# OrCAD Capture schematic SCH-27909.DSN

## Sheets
1 4. Power Supply, Battery, uSD: size C; title: FRDM-FXS-MULTI; rev: C; company: Freescale Semiconductor; note: SCH-27909 | PDF: SPF-27909; note: 6501 William Cannon Drive West; note: Austin, TX 78735-8598
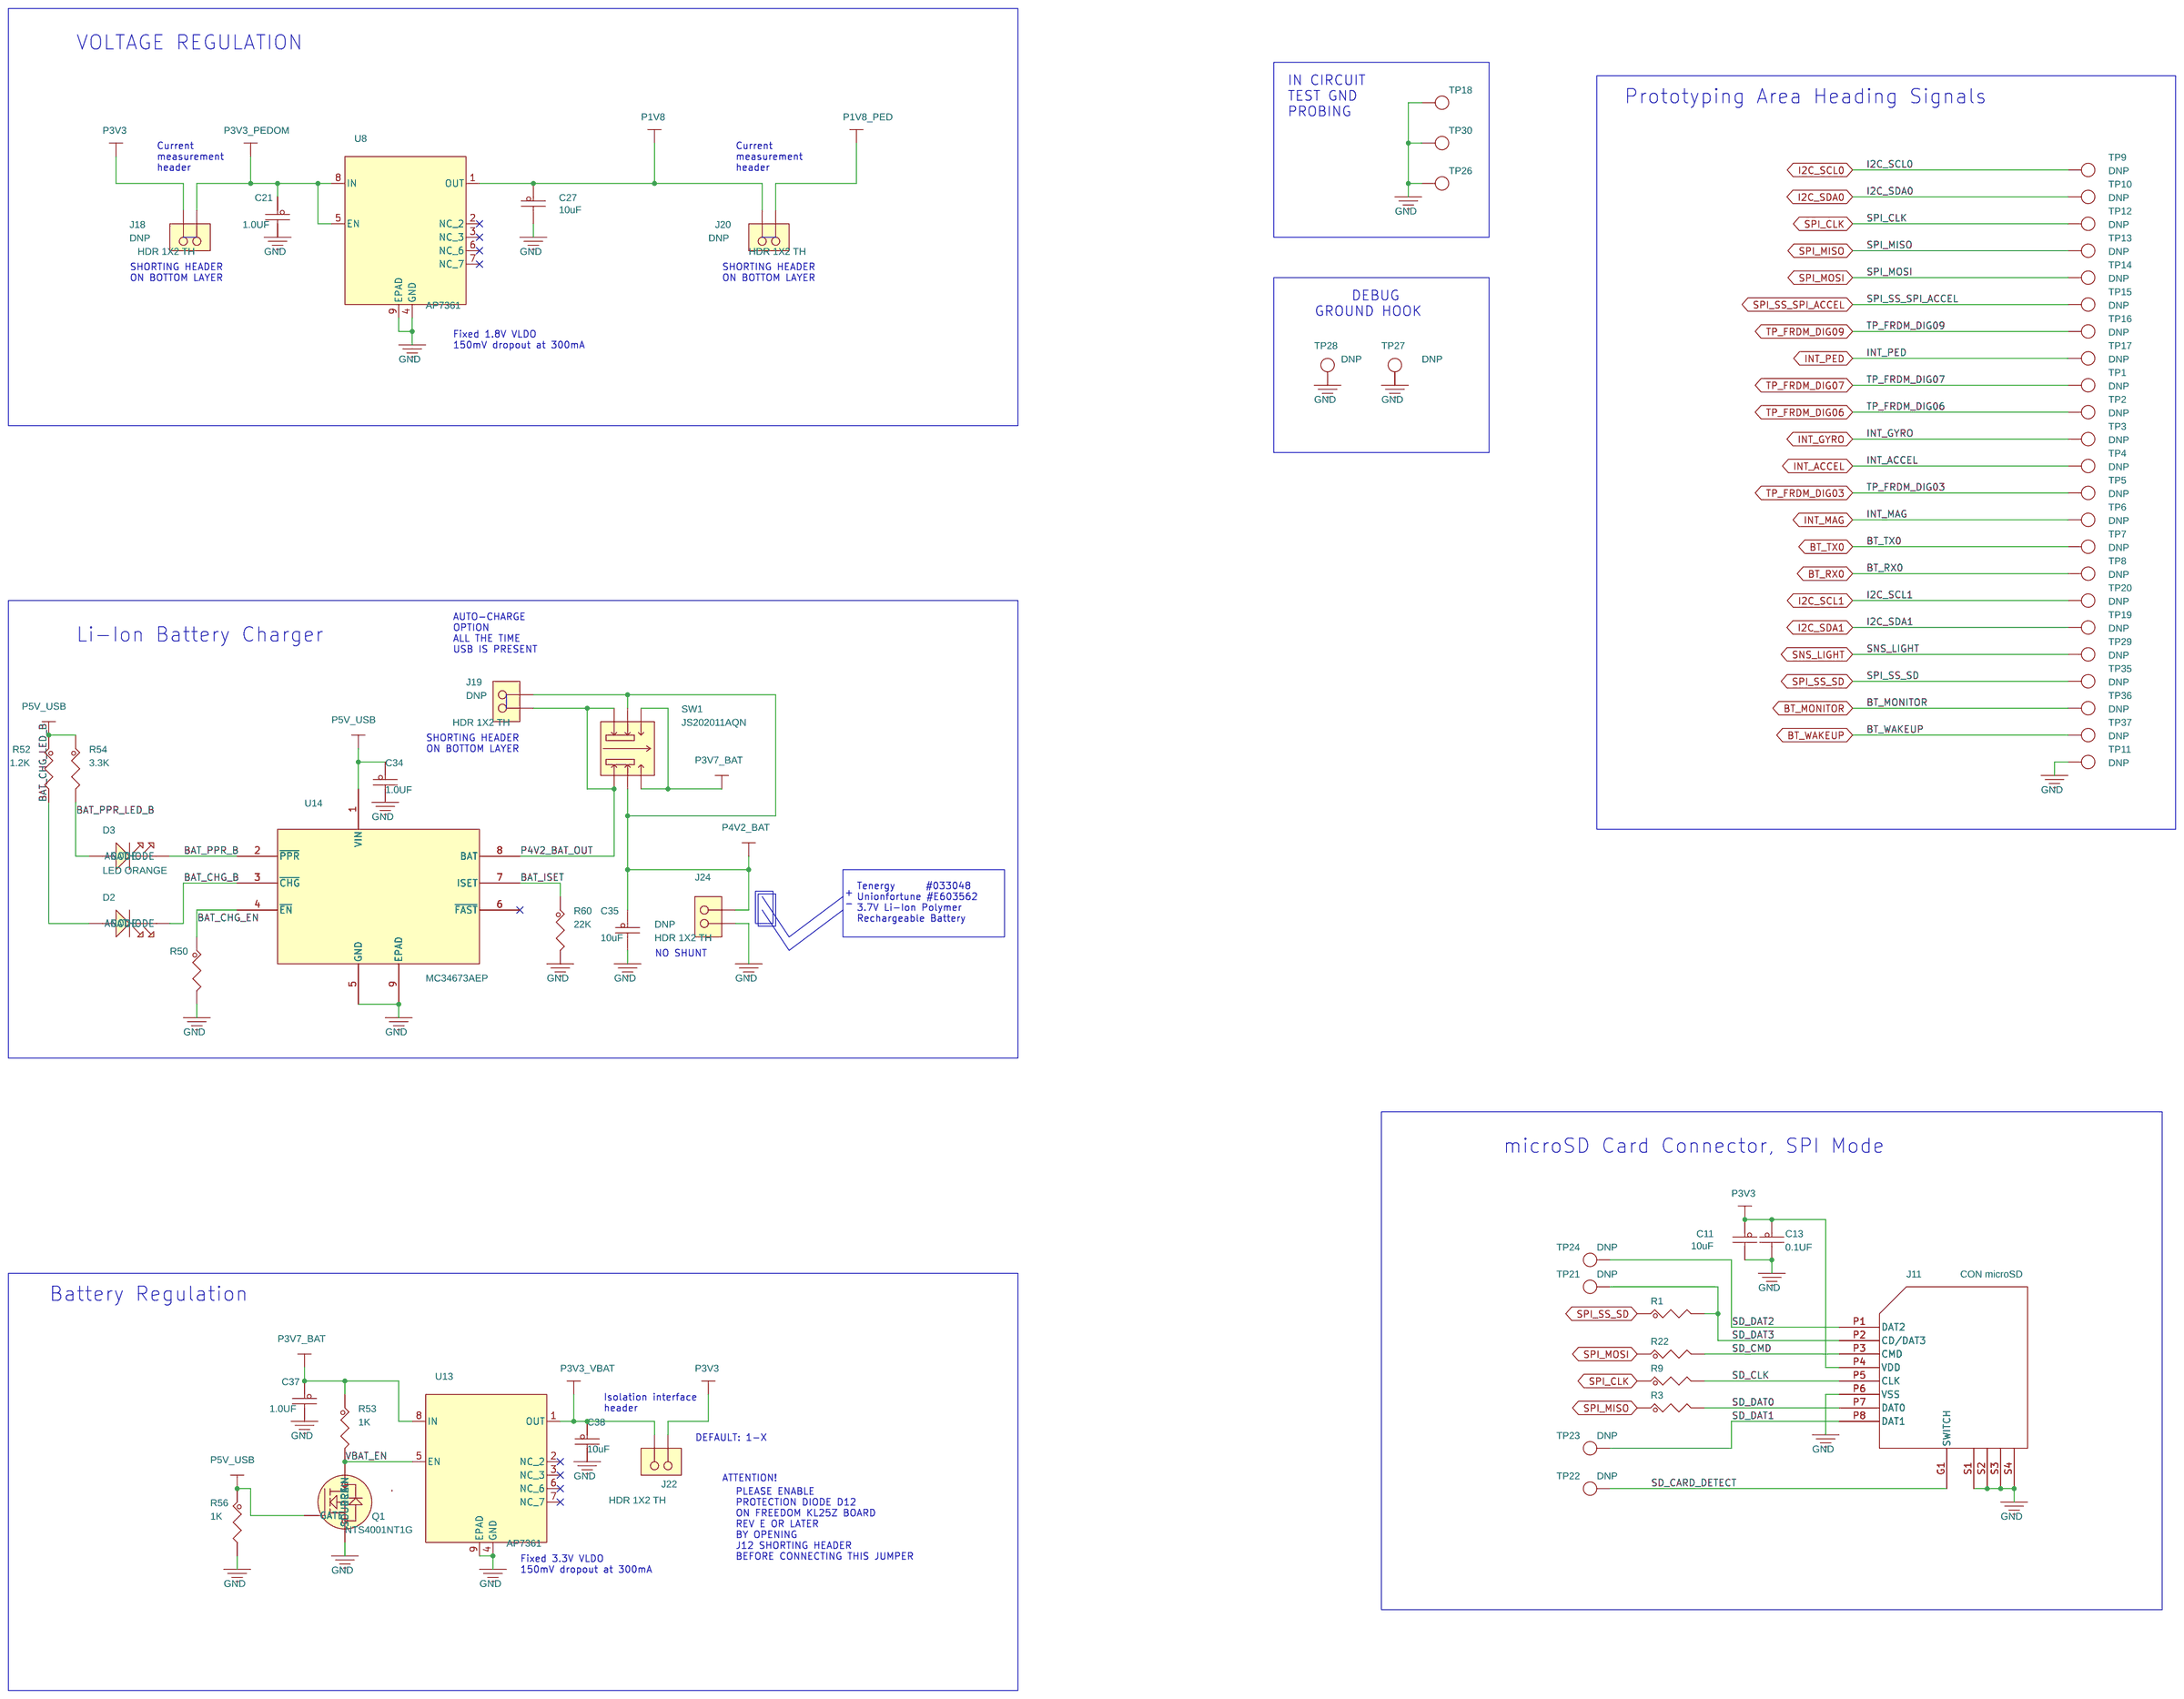
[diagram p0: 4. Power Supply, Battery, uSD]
2 1. Title Page
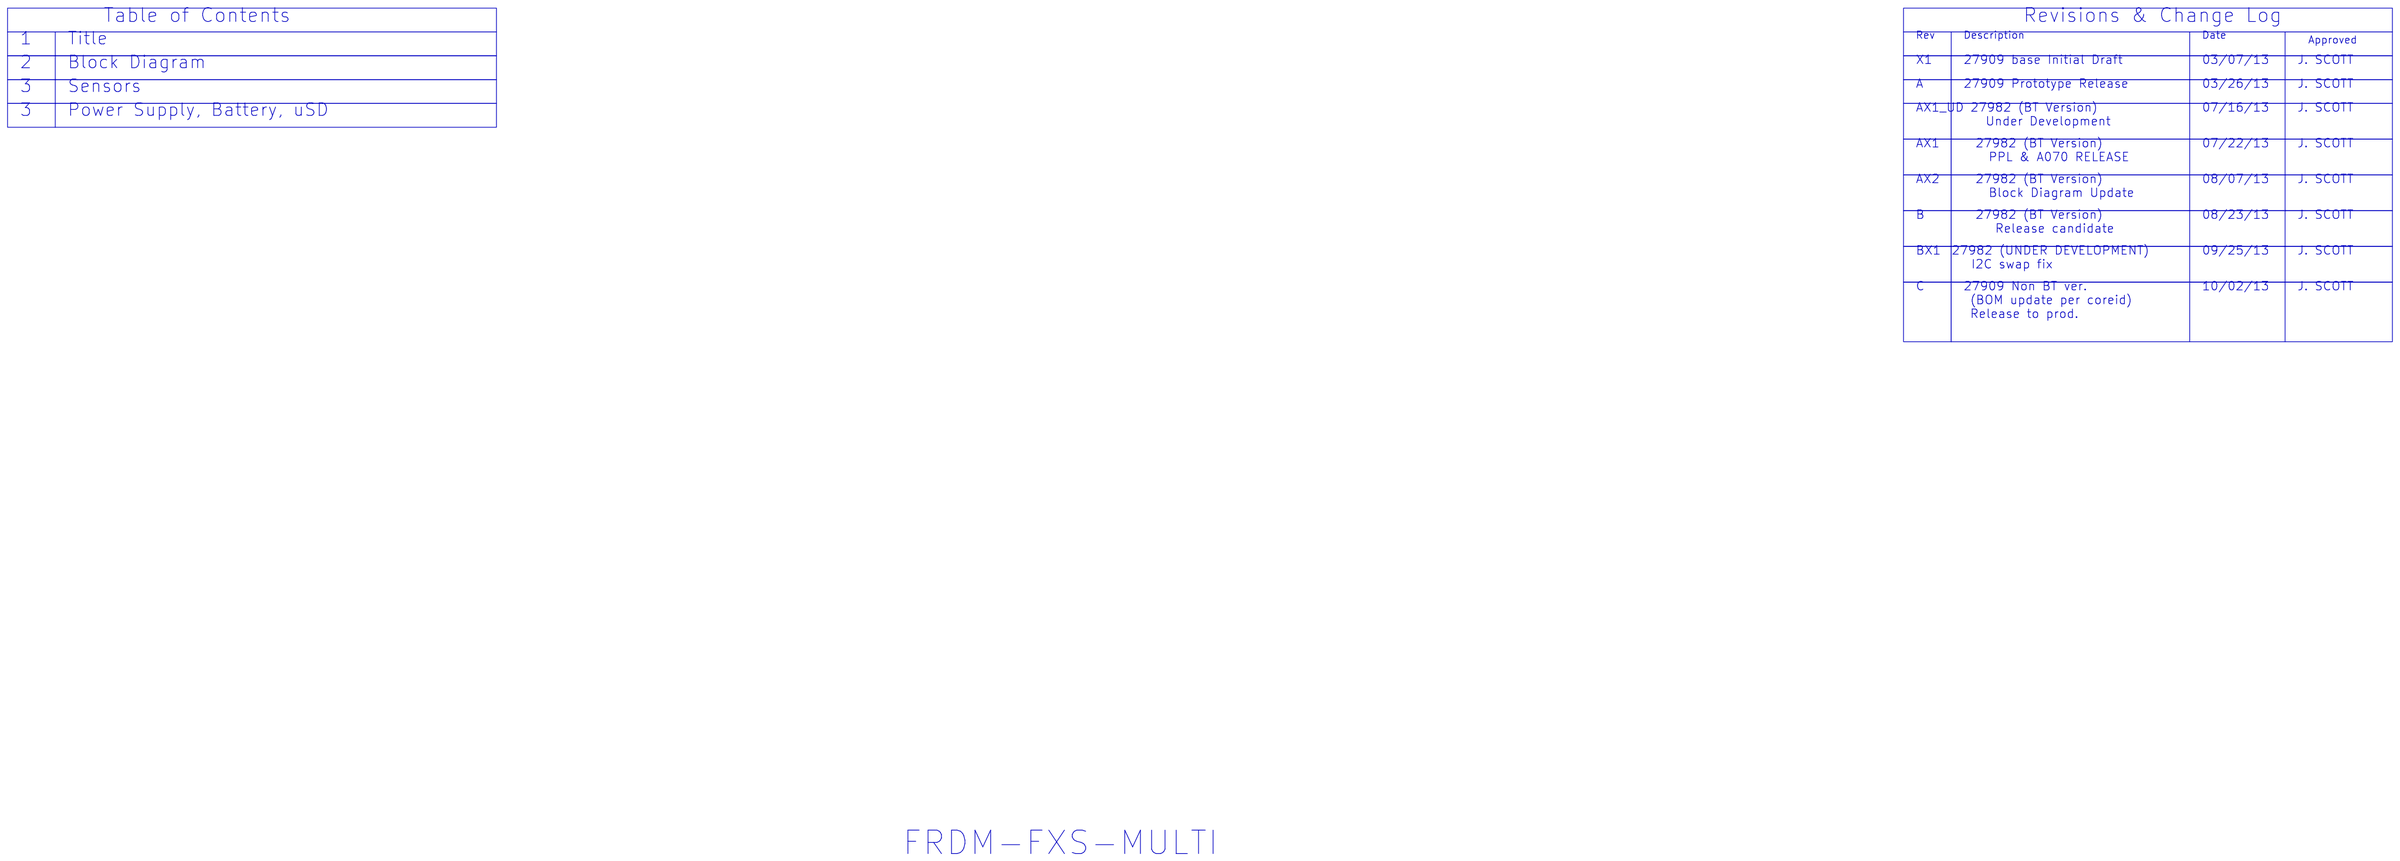
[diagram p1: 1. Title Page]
3 2. Block Diagram
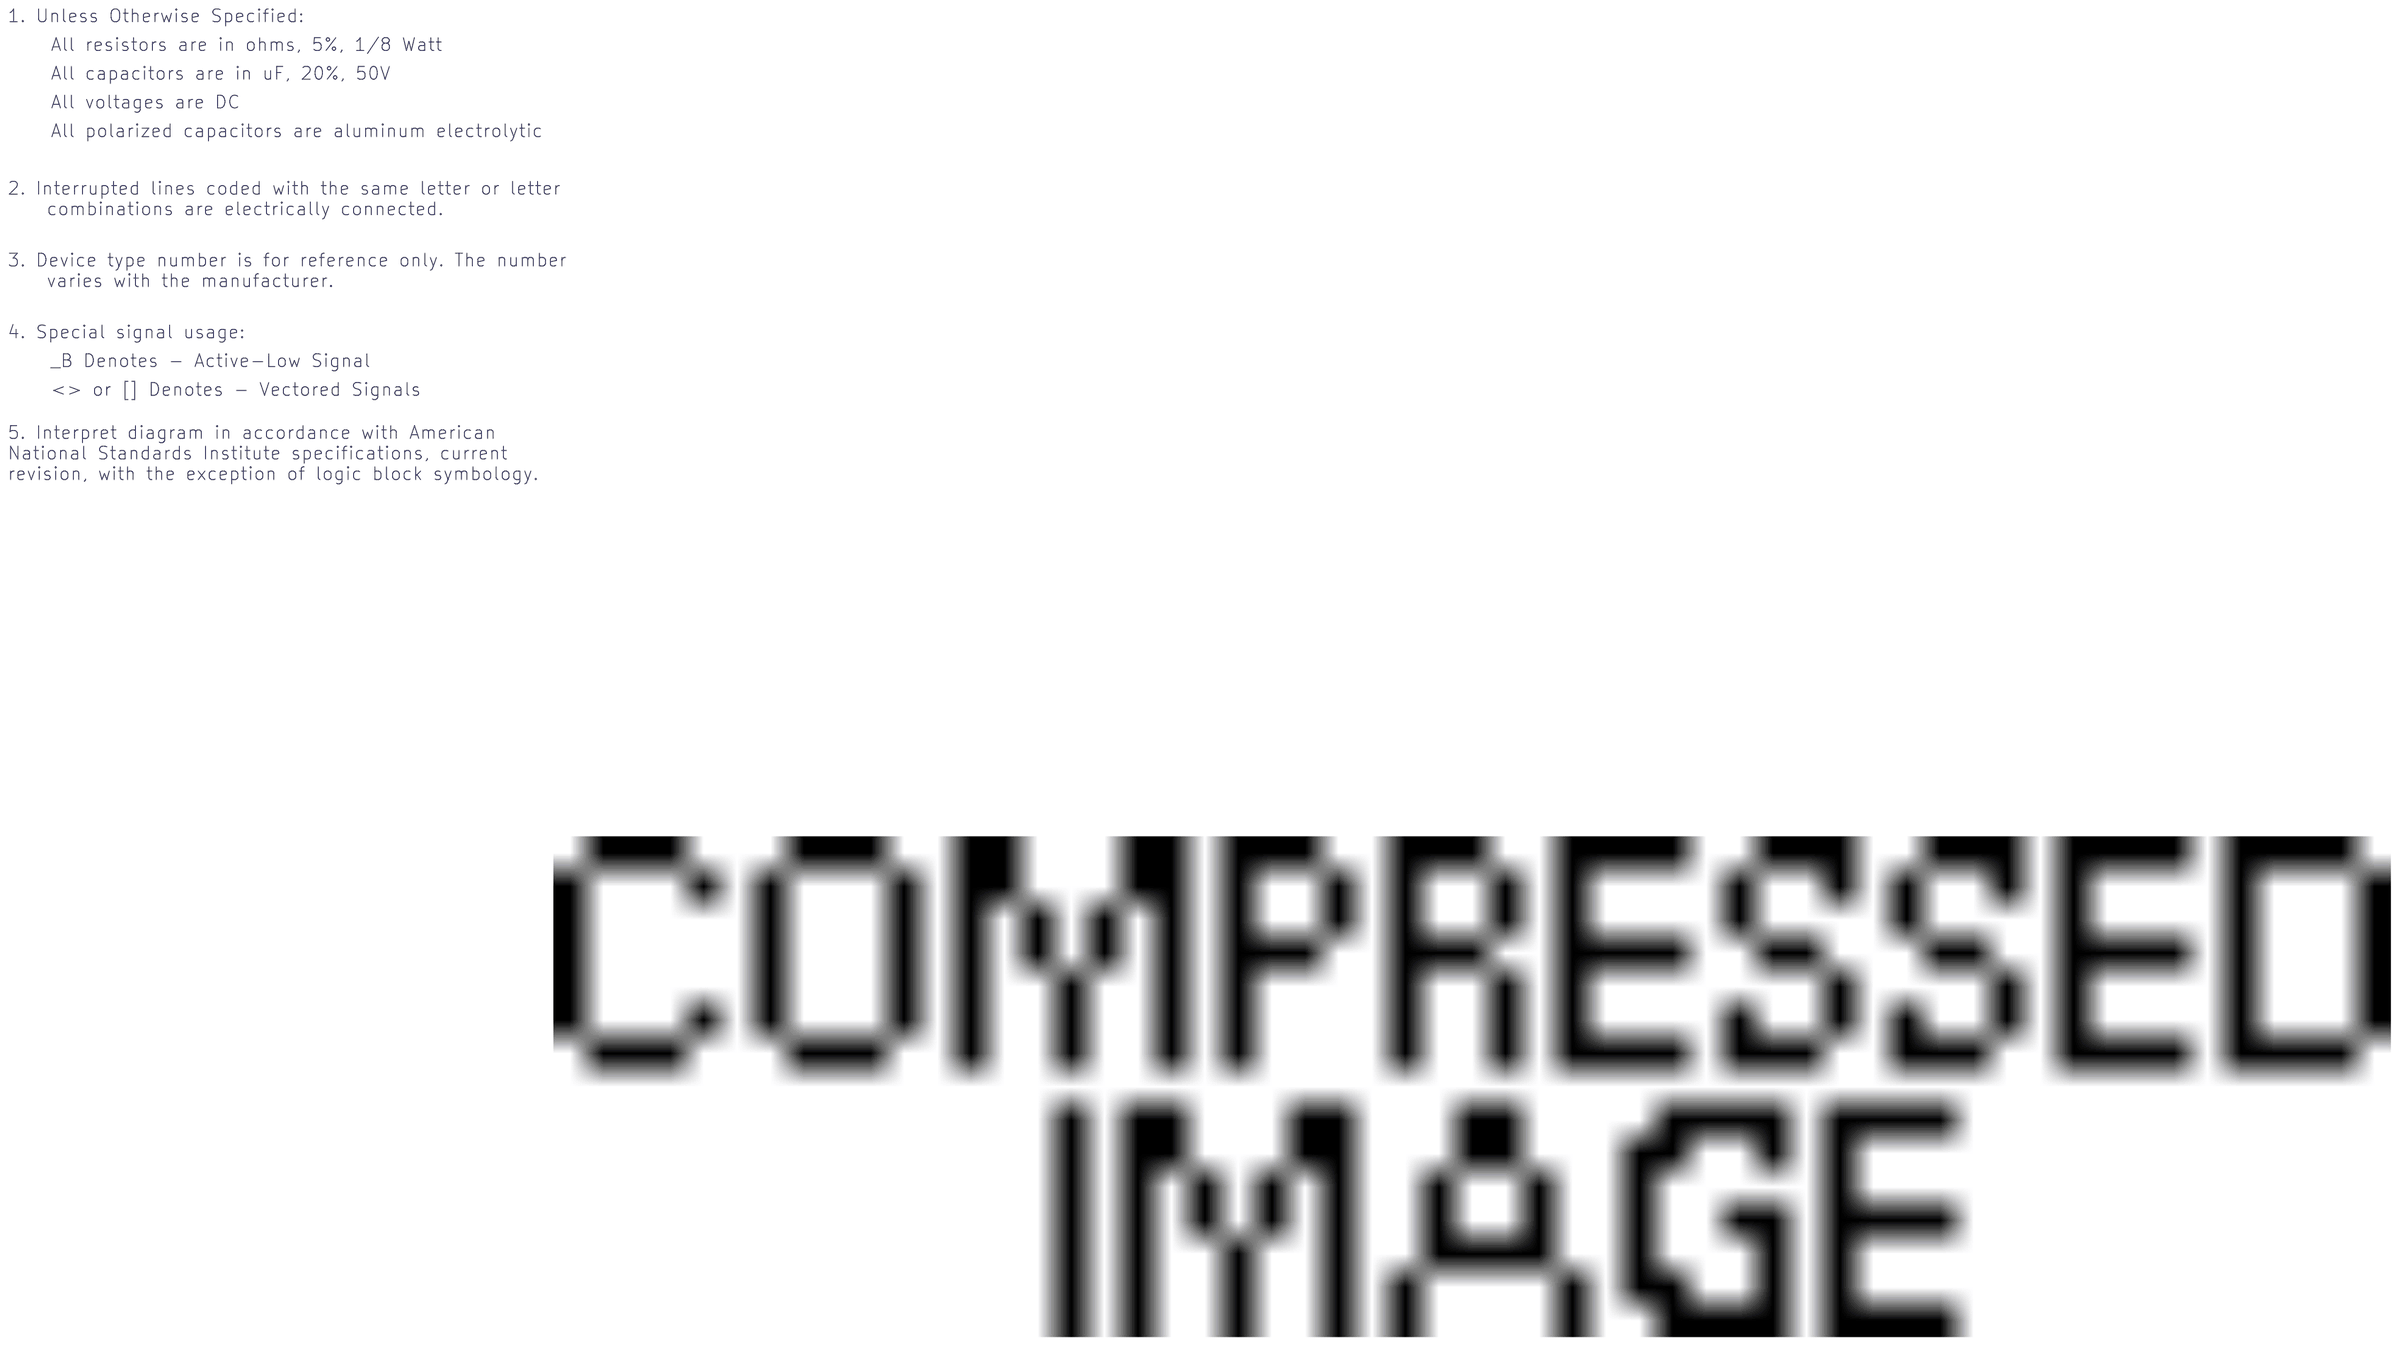
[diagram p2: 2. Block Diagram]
4 3. Sensors: size C
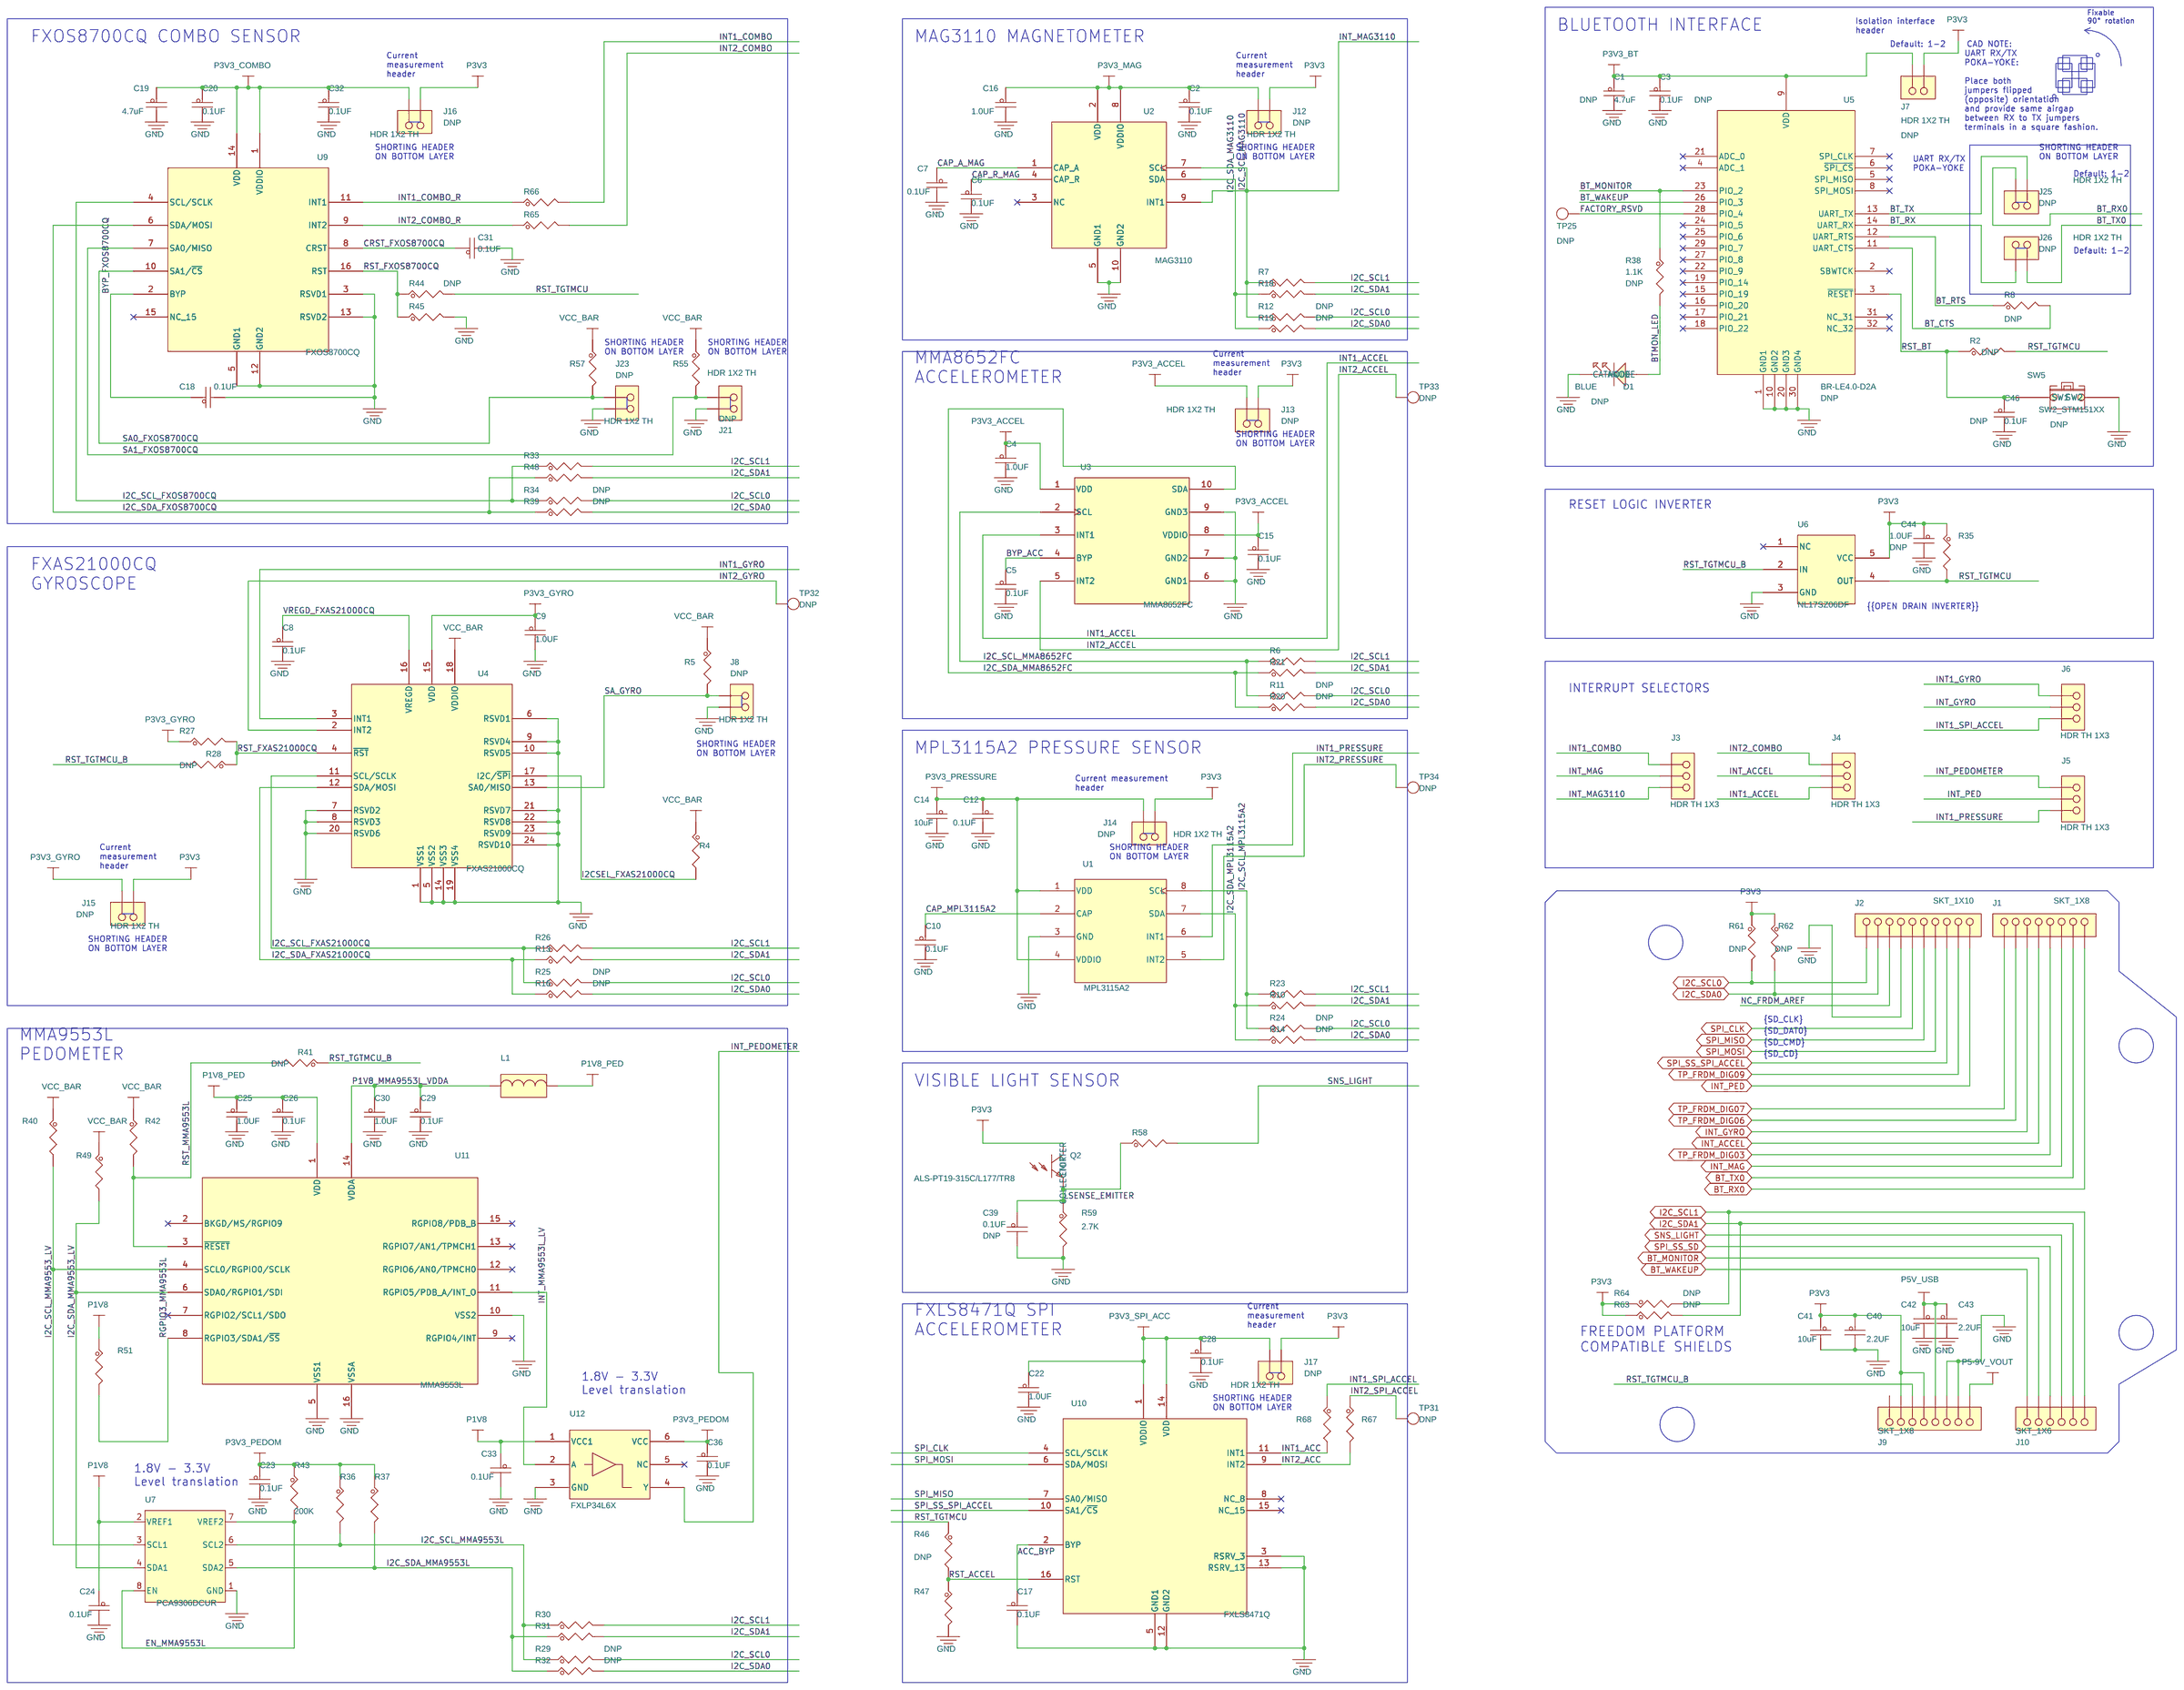
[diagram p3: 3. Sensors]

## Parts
sheet 3. Sensors
C1  4.7uF  [CC0402_25]
C2  0.1UF  [CC0402_25]
C3  0.1UF  [CC0402_25]
C4  1.0UF  [CC0402_25]
C5  0.1UF  [CC0402_25]
C6  0.1UF  [CC0402_25]
C7  0.1UF  [CC0402_25]
C8  0.1UF  [CC0402_25]
C9  1.0UF  [CC0402_25]
C10  0.1UF  [CC0402_25]
C12  0.1UF  [CC0402_25]
C14  10uF  [CC0603_OV]
C15  0.1UF  [CC0402_25]
C16  1.0UF  [CC0402_25]
C17  0.1UF  [CC0402_25]
C18  0.1UF  [CC0402_25]
C19  4.7uF  [CC0402_25]
C20  0.1UF  [CC0402_25]
C22  1.0UF  [CC0402_25]
C23  0.1UF  [CC0402_25]
C24  0.1UF  [CC0402_25]
C25  1.0UF  [CC0402_25]
C26  0.1UF  [CC0402_25]
C28  0.1UF  [CC0402_25]
C29  0.1UF  [CC0402_25]
C30  1.0UF  [CC0402_25]
C31  0.1UF  [CC0402_25]
C32  0.1UF  [CC0402_25]
C33  0.1UF  [CC0402_25]
C36  0.1UF  [CC0402_25]
C39  0.1UF  [CC0402_25]
C40  2.2UF  [CC0603_OV]
C41  10uF  [CC0603_OV]
C42  10uF  [CC0603_OV]
C43  2.2UF  [CC0603_OV]
C44  1.0UF  [CC0402_25]
C46  0.1UF  [CC0402_25]
D1  BLUE  [LED_0603]
J1  SKT_1X8  [con_skt1x8_th]
J2  SKT_1X10  [con_skt1x10_th]
J3  HDR TH 1X3  [HDR103]
J4  HDR TH 1X3  [HDR103]
J5  HDR TH 1X3  [HDR103]
J6  HDR TH 1X3  [HDR103]
J7  HDR 1X2 TH  [HDR102]
J8  HDR 1X2 TH  [SH_HDR102_BOTTOM]
J9  SKT_1X8  [con_skt1x8_th]
J10  SKT_1X6  [con_skt1x6_th]
J12  HDR 1X2 TH  [SH_HDR102_BOTTOM]
J13  HDR 1X2 TH  [SH_HDR102_BOTTOM]
J14  HDR 1X2 TH  [SH_HDR102_BOTTOM]
J15  HDR 1X2 TH  [SH_HDR102_BOTTOM]
J16  HDR 1X2 TH  [SH_HDR102_BOTTOM]
J17  HDR 1X2 TH  [SH_HDR102_BOTTOM]
J21  HDR 1X2 TH  [SH_HDR102_BOTTOM]
J23  HDR 1X2 TH  [SH_HDR102_BOTTOM]
J25  HDR 1X2 TH  [SH_HDR102_BOTTOM]
J26  HDR 1X2 TH  [SH_HDR102_BOTTOM]
L1  330 OHM  [IND_0805]
Q2  ALS-PT19-315C/L177/TR8  [phtrans_1p9x1]
R2  0  [RC0603_OV]
R4  10K  [RC0603_OV]
R5  10K  [RC0603_OV]
R6  0  [RC0603_OV]
R7  0  [RC0603_OV]
R8  0  [RC0603_OV]
R10  0  [RC0603_OV]
R11  0  [RC0603_OV]
R12  0  [RC0603_OV]
R13  0  [RC0603_OV]
R14  0  [RC0603_OV]
R16  0  [RC0603_OV]
R18  0  [RC0603_OV]
R19  0  [RC0603_OV]
R20  0  [RC0603_OV]
R21  0  [RC0603_OV]
R23  0  [RC0603_OV]
R24  0  [RC0603_OV]
R25  0  [RC0603_OV]
R26  0  [RC0603_OV]
R27  10K  [RC0603_OV]
R28  0  [RC0603_OV]
R29  0  [RC0603_OV]
R30  0  [RC0603_OV]
R31  0  [RC0603_OV]
R32  0  [RC0603_OV]
R33  0  [RC0603_OV]
R34  0  [RC0603_OV]
R35  10K  [RC0603_OV]
R36  4.7K  [RC0603_OV]
R37  4.7K  [RC0603_OV]
R38  1.1K  [RC0603_OV]
R39  0  [RC0603_OV]
R40  4.7K  [RC0603_OV]
R41  0  [RC0603_OV]
R42  4.7K  [RC0603_OV]
R43  200K  [RC0603_OV]
R44  0  [RC0603_OV]
R45  10K  [RC0603_OV]
R46  0  [RC0603_OV]
R47  10K  [RC0603_OV]
R48  0  [RC0603_OV]
R49  4.7K  [RC0603_OV]
R51  4.7K  [RC0603_OV]
R55  10K  [RC0603_OV]
R57  10K  [RC0603_OV]
R58  0  [RC0603_OV]
R59  2.7K  [RC0603_OV]
R61  10K  [RC0603_OV]
R62  10K  [RC0603_OV]
R63  10K  [RC0603_OV]
R64  10K  [RC0603_OV]
R65  0  [RC0603_OV]
R66  0  [RC0603_OV]
R67  0  [RC0603_OV]
R68  0  [RC0603_OV]
SW5  SW2_STM151XX  [sw2_4x3mm_sm]
TP25  TPAD_030  [TPAD_030]
TP31  TPAD_030  [TPAD_030]
TP32  TPAD_030  [TPAD_030]
TP33  TPAD_030  [TPAD_030]
TP34  TPAD_030  [TPAD_030]
U1  MPL3115A2  [LGA8_1P25_3X5_0P5]
U2  MAG3110  [DFN_10_0P4_2X2_A]
U3  MMA8652FC  [DFN_10_0P4_2X2]
U4  FXAS21000CQ  [QFN24_0P5_4X4_ASYM_EXP]
U5  BR-LE4.0-D2A  [bluetooth_module_18x12]
U6  NL17SZ06DF  [sot353]
U7  PCA9306DCUR  [ssop8_dcu]
U9  FXOS8700CQ  [qfn5x3_0p5_3x3]
U10  FXLS8471Q  [QFN5X3_0P5_3X3]
U11  MMA9553L  [LGA16_0P5_3X3_A]
U12  FXLP34L6X  [MICROPAK_6P]
sheet 4. Power Supply, Battery, uSD
C11  10uF  [CC0603_OV]
C13  0.1UF  [CC0402_25]
C21  1.0UF  [CC0402_25]
C27  10uF  [CC0603_OV]
C34  1.0UF  [CC0402_25]
C35  10uF  [CC0603_OV]
C37  1.0UF  [CC0402_25]
C38  10uF  [CC0603_OV]
D2  LED GREEN  [LED_0603]
D3  LED ORANGE  [LED_0603]
J11  CON microSD  [con8_sdcard_push_sm]
J18  HDR 1X2 TH  [SH_HDR102_BOTTOM]
J19  HDR 1X2 TH  [SH_HDR102_BOTTOM]
J20  HDR 1X2 TH  [SH_HDR102_BOTTOM]
J22  HDR 1X2 TH  [HDR102]
J24  HDR 1X2 TH  [HDR102]
Q1  NTS4001NT1G  [sc70_3]
R1  0  [RC0603_OV]
R3  0  [RC0603_OV]
R9  0  [RC0603_OV]
R22  0  [RC0603_OV]
R50  0  [RC0603_OV]
R52  1.2K  [RC0603_OV]
R53  1K  [RC0402_25]
R54  3.3K  [RC0603_OV]
R56  1K  [RC0402_25]
R60  22K  [RC0603_OV]
SW1  JS202011AQN  [sw6_2p5_9x3p6]
TP1  TEST POINT WHITE  [TEST_LOOP]
TP2  TEST POINT WHITE  [TEST_LOOP]
TP3  TEST POINT WHITE  [TEST_LOOP]
TP4  TEST POINT WHITE  [TEST_LOOP]
TP5  TEST POINT WHITE  [TEST_LOOP]
TP6  TEST POINT WHITE  [TEST_LOOP]
TP7  TEST POINT WHITE  [TEST_LOOP]
TP8  TEST POINT WHITE  [TEST_LOOP]
TP9  TEST POINT WHITE  [TEST_LOOP]
TP10  TEST POINT WHITE  [TEST_LOOP]
TP11  TEST POINT WHITE  [TEST_LOOP]
TP12  TEST POINT WHITE  [TEST_LOOP]
TP13  TEST POINT WHITE  [TEST_LOOP]
TP14  TEST POINT WHITE  [TEST_LOOP]
TP15  TEST POINT WHITE  [TEST_LOOP]
TP16  TEST POINT WHITE  [TEST_LOOP]
TP17  TEST POINT WHITE  [TEST_LOOP]
TP18  TPAD_030  [TPAD_030]
TP19  TEST POINT WHITE  [TEST_LOOP]
TP20  TEST POINT WHITE  [TEST_LOOP]
TP21  TEST POINT WHITE  [TEST_LOOP]
TP22  TEST POINT WHITE  [TEST_LOOP]
TP23  TEST POINT WHITE  [TEST_LOOP]
TP24  TEST POINT WHITE  [TEST_LOOP]
TP26  TPAD_030  [TPAD_030]
TP27  TEST POINT WHITE  [TEST_LOOP]
TP28  TEST POINT WHITE  [TEST_LOOP]
TP29  TEST POINT WHITE  [TEST_LOOP]
TP30  TPAD_030  [TPAD_030]
TP35  TEST POINT WHITE  [TEST_LOOP]
TP36  TEST POINT WHITE  [TEST_LOOP]
TP37  TEST POINT WHITE  [TEST_LOOP]
U8  AP7361  [tdfn8_0p65_3x3]
U13  AP7361  [tdfn8_0p65_3x3]
U14  MC34673AEP  [DFN_8_0P5_2X3]

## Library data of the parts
C1 = CAP_NP: CAP CER 4.7UF 6.3V 20% X5R 0402; AGILE_PN: 150-78463; ASSY_OPT: DNP; CAD_APPROVED: Yes; FPLIST: CC0402_25,CC0402_HD,0402_CC; HEIGHT: 0.65MM; MFG_NAME01: VENKEL COMPANY; MFG_PN01: C0402X5R6R3-475MNP; ROHS: Yes; Tolerance: 20%; VOLTAGE: 6.3V
C2 C5-C8 C10 C12 C13 C15 C17 C18 C20 C23 C24 C26 C28 C29 C31-C33 C36 = CAP_NP: CAP CER 0.1UF 10V 10% X5R 0402; AGILE_PN: 150-75634; CAD_APPROVED: Yes; FPLIST: CC0402_25,CC0402_HD,0402_CC; HEIGHT: 0.64MM; MFG_NAME01: KEMET; MFG_PN01: C0402C104K8PAC; ROHS: Yes; Tolerance: 10%; VOLTAGE: 10V
C3 C39 C46 = CAP_NP: CAP CER 0.1UF 10V 10% X5R 0402; AGILE_PN: 150-75634; ASSY_OPT: DNP; CAD_APPROVED: Yes; FPLIST: CC0402_25,CC0402_HD,0402_CC; HEIGHT: 0.64MM; MFG_NAME01: KEMET; MFG_PN01: C0402C104K8PAC; ROHS: Yes; Tolerance: 10%; VOLTAGE: 10V
C4 C9 C16 C21 C22 C25 C30 C34 C37 = CAP_NP: CAP CER 1.0UF 10V 10% X5R 0402; AGILE_PN: 150-75772; CAD_APPROVED: Yes; FPLIST: CC0402_25,CC0402_HD,0402_CC; HEIGHT: 0.6MM; MFG_NAME01: YAGEO AMERICA; MFG_PN01: CC0402KRX5R6BB105; ROHS: Yes; VOLTAGE: 10V
C11 C14 C27 C35 C38 C41 C42 = CAP_NP: CAP CER 10UF 10V 20% X5R 0603; AGILE_PN: 150-78609; CAD_APPROVED: Yes; FPLIST: CC0603_OV,CC0603,0603_CC; HEIGHT: 1.016MM; MFG_NAME01: TAIYO YUDEN; MFG_PN01: LMK107BJ106MALTD; ROHS: Yes; VOLTAGE: 10V
C19 = CAP_NP: CAP CER 4.7UF 6.3V 20% X5R 0402; AGILE_PN: 150-78463; CAD_APPROVED: Yes; FPLIST: CC0402_25,CC0402_HD,0402_CC; HEIGHT: 0.65MM; MFG_NAME01: VENKEL COMPANY; MFG_PN01: C0402X5R6R3-475MNP; ROHS: Yes; Tolerance: 20%; VOLTAGE: 6.3V
C40 C43 = CAP_NP: CAP CER 2.2UF 10V 10% X7R 0603; AGILE_PN: 150-78564; CAD_APPROVED: Yes; FPLIST: CC0603_OV,CC0603,0603_CC; HEIGHT: 1.25MM; MFG_NAME01: TAIYO YUDEN; MFG_PN01: LMK107B7225KA-T; ROHS: Yes; Tolerance: 10%; VOLTAGE: 10V
C44 = CAP_NP: CAP CER 1.0UF 10V 10% X5R 0402; AGILE_PN: 150-75772; ASSY_OPT: DNP; CAD_APPROVED: Yes; FPLIST: CC0402_25,CC0402_HD,0402_CC; HEIGHT: 0.6MM; MFG_NAME01: YAGEO AMERICA; MFG_PN01: CC0402KRX5R6BB105; ROHS: Yes; VOLTAGE: 10V
D1 = LED: LED BLUE -- 20MA SMT; AGILE_PN: 370-75078; ASSY_OPT: DNP; CAD_APPROVED: Yes; HEIGHT: 0.8MM; MFG_NAME01: LITE ON; MFG_PN01: LTST-C190TBKT; ROHS: Yes
J1 J9 = CONN_HDR_8X1: CON 1X8 SKT TH 100MIL SP 340H AU 394L; AGILE_PN: 210-80359; CAD_APPROVED: Yes; HEIGHT: 8.64MM; MFG_NAME01: SAMTEC; MFG_PN01: SSQ-108-03-F-S; ROHS: Yes
J2 = CONN_HDR_10X1: CON 1X10 SKT TH 100MIL SP 340H AU 394L; AGILE_PN: 210-80360; CAD_APPROVED: Yes; HEIGHT: 8.64MM; MFG_NAME01: SAMTEC; MFG_PN01: SSQ-110-03-F-S; ROHS: Yes
J3-J6 = CONN_HDR_3X1: HDR 1X3 TH 100MIL SP 339H AU 100L; AGILE_PN: 210-75726; CAD_APPROVED: Yes; HEIGHT: 8.65MM; MFG_NAME01: SAMTEC; MFG_PN01: TSW-103-07-G-S; ROHS: Yes
J7 J8 J12-J21 J23-J26 = CONN_HDR_2X1: HDR 1X2 TH 100MIL SP 339H AU 98L; AGILE_PN: 210-75439; ASSY_OPT: DNP; CAD_APPROVED: YES; FPLIST: HDR102,SH_HDR102_BOTTOM; HEIGHT: 8.71 MM; MFG_NAME01: SAMTEC; MFG_PN01: TSW-102-07-G-S; ROHS: Yes
J10 = CONN_HDR_6X1: CON 1X6 SKT TH 100MIL SP 340H AU 394L; AGILE_PN: 210-80357; CAD_APPROVED: Yes; HEIGHT: 8.64MM; MFG_NAME01: SAMTEC; MFG_PN01: SSQ-106-03-F-S; ROHS: Yes
L1 = BEAD: IND FER BEAD 330OHM@100MHZ 2.5A -- SMT; AGILE_PN: 180-30021; CAD_APPROVED: YES; HEIGHT: 1.05 MM; MFG_NAME01: TDK; MFG_PN01: MPZ2012S331A; PART_TYPE: FERRITE; ROHS: Yes; Tolerance: 25%
Q2 = PT12_PHTRANS_2P: TRAN NPN PHOTO 2.5-5.5V 630NM SMT; AGILE_PN: 480-78363; CAD_APPROVED: Yes; HEIGHT: 0.7MM; MFG_NAME01: EVERLIGHT INTERNATIONAL CORPORATION; ROHS: Yes
R2 R8 R11 R12 R14 R16 R19 R20 R24 R25 R28 R29 R32 R34 R39 R41 R44 R46 = RES: RES MF ZERO OHM 1/10W -- 0603; AGILE_PN: 470-75407; ASSY_OPT: DNP; CAD_APPROVED: Yes; FPLIST: RC0603_OV,RC0603,R603-X2,0603_CC; MFG_NAME01: VISHAY INTERTECHNOLOGY; MFG_PN01: CRCW06030000Z0EA; ROHS: Yes; Tolerance: 1%
R4 R5 R27 R35 R45 R47 R55 R57 = RES: RES MF 10K 1/10W 5% 0603; AGILE_PN: 470-75410; CAD_APPROVED: Yes; FPLIST: RC0603_OV,RC0603,0603_CC; MFG_NAME01: KOA SPEER; MFG_PN01: RK73B1JTTD103J; ROHS: Yes; Tolerance: 5%
R1 R3 R6 R7 R9 R10 R13 R18 R21-R23 R26 R30 R31 R33 R48 R50 R58 R65-R68 = RES: RES MF ZERO OHM 1/10W -- 0603; AGILE_PN: 470-75407; CAD_APPROVED: Yes; FPLIST: RC0603_OV,RC0603,R603-X2,0603_CC; MFG_NAME01: VISHAY INTERTECHNOLOGY; MFG_PN01: CRCW06030000Z0EA; ROHS: Yes; Tolerance: 1%
R36 R37 R40 R42 R49 R51 = RES: RES MF 4.7K 1/10W 5% 0603; AGILE_PN: 470-75414; CAD_APPROVED: Yes; FPLIST: RC0603_OV,RC0603,0603_CC; MFG_NAME01: VISHAY INTERTECHNOLOGY; MFG_PN01: CRCW06034K70JNEA; ROHS: Yes; Tolerance: 5%
R38 = RES: RES MF 1.1K 1/10W 1% 0603; AGILE_PN: 470-77980; ASSY_OPT: DNP; CAD_APPROVED: Yes; FPLIST: RC0603_OV,RC0603,0603_CC; MFG_NAME01: KOA SPEER; MFG_PN01: RK73H1JTTD1101F; ROHS: Yes; Tolerance: 1%
R43 = RES: RES MF 200K 1/10W 5% 0603; AGILE_PN: 470-75783; CAD_APPROVED: Yes; FPLIST: RC0603_OV,RC0603,0603_CC; MFG_NAME01: VENKEL COMPANY; MFG_PN01: CR0603-10W-204JT; ROHS: Yes; Tolerance: 5%
R59 = RES: RES MF 2.7K 1/10W 5% 0603; AGILE_PN: 470-75910; CAD_APPROVED: Yes; FPLIST: RC0603_OV,RC0603,0603_CC; MFG_NAME01: KOA SPEER; MFG_PN01: RK73B1JTTD272J; ROHS: Yes; Tolerance: 5%
R61-R64 = RES: RES MF 10K 1/10W 5% 0603; AGILE_PN: 470-75410; ASSY_OPT: DNP; CAD_APPROVED: Yes; FPLIST: RC0603_OV,RC0603,0603_CC; MFG_NAME01: KOA SPEER; MFG_PN01: RK73B1JTTD103J; ROHS: Yes; Tolerance: 5%
SW5 = SW2_STM151XX: SW SPST MOM NO TACT 12V 50MA SMT; AGILE_PN: 510-76958; ASSY_OPT: DNP; CAD_APPROVED: Yes; HEIGHT: 2MM; MFG_NAME01: E SWITCH; MFG_PN01: TL1015BF160QG; ROHS: Yes
TP25 TP31-TP34 = TestLoop: TEST POINT PAD 30MIL DIA SMT, NO PART TO ORDER; AGILE_PN: 211-76642; ASSY_OPT: DNP; CAD_APPROVED: Yes; HEIGHT: 0.1MM; MFG_NAME01: NOTACOMPONENT; MFG_PN01: NOTACOMPONENT; ROHS: Yes
U1 = PPL3115A2_LGA_8P: IC ALTIMETER I2C 50-115KPA 1.96-3.6V LGA8; AGILE_PN: 315-79136; CAD_APPROVED: Yes; HEIGHT: 1.2MM; MFG_NAME01: FREESCALE SEMICONDUCTOR; ROHS: Yes
U2 = MAG3112_DFN_10P: IC 3-AXIS DIGITAL MAGNETOMETER 1.95-3.6V DFN10; AGILE_PN: 312-79970; CAD_APPROVED: Yes; FPLIST: DFN_10_0P4_2X2,DFN_10_0P4_2X2_A; HEIGHT: 0.9MM; MFG_NAME01: FREESCALE SEMICONDUCTOR; MFG_PN01: MAG3110FC; ROHS: Yes
U3 = MMA8652_DFN10: IC 3-AXIS 12-BIT DIGITAL ACCELEROMETER 1.95-3.6V DFN10; AGILE_PN: 312-80113; CAD_APPROVED: Yes; HEIGHT: 1MM; MFG_NAME01: Freescale Semiconductor; ROHS: Yes
U4 = LEON_24P: IC SENSOR GYROSCOPE 3-AXIS FIFO 1.95-3.6V QFN24; AGILE_PN: TMP-WF-15891; CAD_APPROVED: Yes; HEIGHT: 1.05MM; MFG_NAME01: Freescale Semiconductor; PRE_APN: 312-80348; ROHS: Yes
U5 = BR-LE4.0-D2A_32P: IC BLUETOOTH 4.0 MODULE WITH ANTENNA 3V SMT; AGILE_PN: 312-80555; ASSY_OPT: DNP; CAD_APPROVED: Yes; HEIGHT: 2MM; MFG_NAME01: BLUERADIOS, INC; ROHS: Yes
U6 = NL17SZ06: IC GATE INV SINGLE 1.65-5.5V SOT353; AGILE_PN: 312-77037; CAD_APPROVED: Yes; HEIGHT: 1.1MM; MFG_NAME01: ON SEMICONDUCTOR; MFG_PN01: NL17SZ06DFT2G; ROHS: Yes
U7 = PCA9306DCUR: IC VXLTR 2BIT BIDIR 1.2-3.3V/1.-5.5V VSSOP8; AGILE_PN: 315-78802; CAD_APPROVED: Yes; HEIGHT: 0.9MM; MFG_NAME01: Texas Instruments; ROHS: Yes
U9 = FXOS8700CQ_QFN_16P: IC ACCELEROMETER AND MAGNETOMETER SENSOR 3-AXIS 2.5V QFN16; AGILE_PN: TMP-WF-16648; CAD_APPROVED: Yes; HEIGHT: 1.25MM; MFG_NAME01: Freescale Semiconductor; PRE_APN: 312-80418; ROHS: Yes
U10 = FXLS8471Q_16P: IC 3-AXIS LIN ACCELEROMETER 14BIT 1.95-3.6V QFN16; AGILE_PN: 315-79718; CAD_APPROVED: Yes; HEIGHT: 1 MM; MFG_NAME01: FREESCALE SEMICONDUCTOR; ROHS: Yes
U11 = MMA9550_LGA_16P: IC ACCELEROMETER SENSOR 3-AXIS DIGITAL 1.8V LGA16; AGILE_PN: 312-80088; CAD_APPROVED: Yes; HEIGHT: 1MM; MFG_NAME01: FREESCALE SEMICONDUCTOR; MFG_PN01: PMMA9553LT; ROHS: Yes
U12 = FXLP34: IC VXLTR SGL 1.0-3.6V MICROPAK6; AGILE_PN: 312-76435; CAD_APPROVED: Yes; HEIGHT: 0.55MM; MFG_NAME01: FAIRCHILD; ROHS: Yes
D2 = LED: LED GRN SGL 20MA 0603; AGILE_PN: 370-76565; CAD_APPROVED: Yes; HEIGHT: 0.67MM; MFG_NAME01: osram; MFG_PN01: LG L29K-G2J1-24-Z; ROHS: Yes
D3 = LED: LED OR SGL 20MA 0603; AGILE_PN: 370-75622; CAD_APPROVED: Yes; HEIGHT: 0.67MM; MFG_NAME01: OSRAM; MFG_PN01: LO L29K-J2L1-24-Z; ROHS: Yes
J11 = CON8_SDCARD_SW: CON 8 SD CARD PUSH SMT 1.1MM SP 75H AU; AGILE_PN: 211-79395; CAD_APPROVED: Yes; HEIGHT: 1.9 MM; MFG_NAME01: MOLEX; MFG_PN01: 1050270001; ROHS: Yes
J22 = CONN_HDR_2X1: HDR 1X2 TH 100MIL SP 339H AU 98L; AGILE_PN: 210-75439; CAD_APPROVED: YES; FPLIST: HDR102,SH_HDR102_BOTTOM; HEIGHT: 8.71 MM; MFG_NAME01: SAMTEC; MFG_PN01: TSW-102-07-G-S; ROHS: Yes
Q1 = MOSFET_N: TRAN NMOS SW 30V 270MA SC-70; AGILE_PN: 480-76278; CAD_APPROVED: Yes; HEIGHT: 1.0MM; MFG_NAME01: ON SEMICONDUCTOR; ROHS: Yes
R52 = RES: RES MF 1.2K 1/10W 1% 0603; AGILE_PN: 470-77984; CAD_APPROVED: Yes; FPLIST: RC0603_OV,RC0603,0603_CC; MFG_NAME01: KOA SPEER; MFG_PN01: RK73H1JTTD1201F; ROHS: Yes; Tolerance: 1%
R53 R56 = RES: RES MF 1.0K 1/16W 5% 0402; AGILE_PN: 470-75555; CAD_APPROVED: Yes; FPLIST: RC0402_25,RC0402_HD,RC0402_X2,0402_CC; MFG_NAME01: VISHAY INTERTECHNOLOGY; MFG_PN01: CRCW04021K00JNED; ROHS: Yes; Tolerance: 5%
R54 = RES: RES MF 3.3K 1/10W 5% 0603; AGILE_PN: 470-75402; CAD_APPROVED: Yes; FPLIST: RC0603_OV,RC0603,0603_CC; MFG_NAME01: KOA SPEER; MFG_PN01: RK73B1JTTD332J; ROHS: Yes; Tolerance: 5%
R60 = RES: RES MF 22K 1/10W 5% 0603; AGILE_PN: 470-75400; CAD_APPROVED: Yes; FPLIST: RC0603_OV,RC0603,0603_CC; MFG_NAME01: KOA SPEER; MFG_PN01: RK73B1JTTD223J; ROHS: Yes; Tolerance: 5%
SW1 = SW_DPDT_6P: SW DPDT RA SLD 0.3A 6V TH; AGILE_PN: 510-77893; CAD_APPROVED: Yes; HEIGHT: 3.5MM; MFG_NAME01: C&K COMPONENTS; ROHS: Yes
TP1-TP17 TP19-TP24 TP27-TP29 TP35-TP37 = TestLoop: TEST POINT WHITE 40 MIL DRILL 180 MIL TH 109L; AGILE_PN: 210-75685; ASSY_OPT: DNP; CAD_APPROVED: Yes; HEIGHT: 4.8 MM; MFG_NAME01: COMPONENTS CORPORATION; MFG_PN01: TP-105-01-09; ROHS: Yes
TP18 TP26 TP30 = TestLoop: TEST POINT PAD 30MIL DIA SMT, NO PART TO ORDER; AGILE_PN: 211-76642; CAD_APPROVED: Yes; HEIGHT: 0.1MM; MFG_NAME01: NOTACOMPONENT; MFG_PN01: NOTACOMPONENT; ROHS: Yes
U8 = AP7361_8P: IC VREG LDO 1.8V 1A 2.2-6V DFN3030-8; AGILE_PN: 315-79771; CAD_APPROVED: Yes; HEIGHT: 0.63MM; MFG_NAME01: Diodes Inc; MFG_PN01: AP7361-18FGE-7; ROHS: Yes
U13 = AP7361_8P: IC VREG LDO 3.3V 1A 2.2-6V DFN3030-8; AGILE_PN: 312-80700; CAD_APPROVED: Yes; HEIGHT: 0.63MM; MFG_NAME01: Diodes Inc; MFG_PN01: AP7361-33FGE-7; ROHS: Yes
U14 = MC34673AEP: IC CHARGER LI-ION/POLYMER BATT 1.2A 20V 8-UDFN; AGILE_PN: 315-76709; CAD_APPROVED: Yes; HEIGHT: 0.65MM; MFG_NAME01: FREESCALE SEMICONDUCTOR; ROHS: Yes

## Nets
GND: C1.2 C2.2 C3.2 C4.2 C5.2 C6.2 C7.2 C8.2 C9.2 C10.2 C11.2 C12.2 C13.2 C14.2 C15.2 C16.2 C17.2 C18.2 C19.2 C20.2 C21.2 C22.2 C23.2 C24.2 C25.2 C26.2 C27.2 C28.2 C29.2 C30.2 C31.2 C32.2 C33.2 C34.2 C35.2 C36.2 C37.2 C38.2 C39.2 C40.2 C41.2 C42.2 C43.2 C44.2 C46.2 D1.C(CATHODE) J2.7 J8.1 J9.6 J9.7 J11.P6(VSS) J11.S1 J11.S2 J11.S3 J11.S4 J21.2 J23.1 J24.1 Q1.2(SOURCE) R45.2 R47.2 R50.2 R56.2 R59.2 R60.2 SW5.2(SW2) TP11.1(Pin1) TP18.1(Pin1) TP26.1(Pin1) TP27.1(Pin1) TP28.1(Pin1) TP30.1(Pin1) U1.3(GND) U2.5(GND1) U2.10(GND2) U3.6(GND1) U3.7(GND2) U3.9(GND3) U4.1(VSS1) U4.5(VSS2) U4.6(RSVD1) U4.7(RSVD2) U4.8(RSVD3) U4.9(RSVD4) U4.10(RSVD5) U4.14(VSS3) U4.19(VSS4) U4.20(RSVD6) U4.21(RSVD7) U4.22(RSVD8) U4.23(RSVD9) U4.24(RSVD10) U5.1(GND1) U5.10(GND2) U5.20(GND3) U5.30(GND4) U6.3(GND) U7.1(GND) U8.4(GND) U8.9(EPAD) U9.3(RSVD1) U9.5(GND1) U9.12(GND2) U9.13(RSVD2) U10.3(RSRV) U10.5(GND1) U10.12(GND2) U10.13(RSRV) U11.5(VSS1) U11.10(VSS2) U11.16(VSSA) U12.3(GND) U13.4(GND) U13.9(EPAD) U14.5(GND) U14.9(EPAD)
P1V8: C24.1 C27.1 C33.1 J20.1 R40.1 R42.1 R49.1 R51.1 U7.2(VREF1) U8.1(OUT) U12.1(VCC1)
P1V8_MMA9553L_VDDA: C29.1 C30.1 L1.1 U11.14(VDDA)
P1V8_PED: C25.1 C26.1 J20.2 L1.2 U11.1(VDD)
P3V3: C11.1 C13.1 C40.1 C41.1 C44.1 J7.1 J9.2 J9.4 J11.P4(VDD) J12.2 J13.2 J14.2 J15.2 J16.1 J17.1 J18.2 J22.2 Q2.1(COLLECTOR) R35.1 R61.1 R62.1 R63.1 R64.1 U6.5(VCC)
P3V3_ACCEL: C4.1 C15.1 J13.1 U3.1(VDD) U3.8(VDDIO)
P3V3_BT: C1.1 C3.1 J7.2 U5.9(VDD)
P3V3_COMBO: C19.1 C20.1 C32.1 J16.2 R55.1 R57.1 U9.1(VDDIO) U9.14(VDD)
P3V3_GYRO: C9.1 J15.1 R4.1 R5.1 R27.1 U4.15(VDD) U4.18(VDDIO)
P3V3_MAG: C2.1 C16.1 J12.1 U2.2(VDD) U2.8(VDDIO)
P3V3_PEDOM: C21.1 C23.1 C36.1 J18.1 R36.1 R37.1 R43.1 U8.5(EN) U8.8(IN) U12.6(VCC)
P3V3_PRESSURE: C12.1 C14.1 J14.1 U1.1(VDD) U1.4(VDDIO)
P3V3_SPI_ACC: C22.1 C28.1 J17.2 U10.1(VDDIO) U10.14(VDD)
P3V3_VBAT: C38.1 J22.1 U13.1(OUT)
P3V7_BAT: C37.1 R53.1 SW1.3 SW1.6 U13.8(IN)
P4V2_BAT: C35.1 J19.2 J24.2 SW1.2 SW1.5
P4V2_BAT_OUT: J19.1 SW1.1 SW1.4 U14.8(BAT)
P5V_USB: C34.1 C42.1 C43.1 J9.5 Q1.1(GATE) R52.1 R54.1 R56.1 U14.1(VIN)
VBAT_EN: Q1.3(DRAIN) R53.2 U13.5(EN)
ACC_BYP: C17.1 U10.2(BYP)
BAT_CHG_B: D2.C(CATHODE) U14.3(~{CHG})
BAT_CHG_EN: R50.1 U14.4(~{EN})
BAT_CHG_LED_B: D2.A(ANODE) R52.2
BAT_ISET: R60.1 U14.7(ISET)
BAT_PPR_B: D3.C(CATHODE) U14.2(~{PPR})
BAT_PPR_LED_B: D3.A(ANODE) R54.2
BT_CTS: R8.2 U5.11(UART_CTS)
BT_MONITOR: J10.2 R38.1 TP36.1(Pin1) U5.23(PIO_2)
BT_RTS: R8.1 U5.12(UART_RTS)
BT_RX: J26.2 U5.14(UART_RX)
BT_RX0: J1.1 J25.2 TP8.1(Pin1)
BT_TX: J25.1 U5.13(UART_TX)
BT_TX0: J1.2 J26.1 TP7.1(Pin1)
BT_WAKEUP: J10.1 TP37.1(Pin1) U5.26(PIO_3)
BTMON_LED: D1.A(ANODE) R38.2
BYP_ACC: C5.1 U3.4(BYP)
BYP_FXOS8700CQ: C18.1 U9.2(BYP)
CAP_A_MAG: C7.1 U2.1(CAP_A)
CAP_MPL3115A2: C10.1 U1.2(CAP)
CAP_R_MAG: C6.1 U2.4(CAP_R)
CRST_FXOS8700CQ: C31.1 U9.8(CRST)
EN_MMA9553L: R43.2 U7.7(VREF2) U7.8(EN)
FACTORY_RSVD: TP25.1(Pin1) U5.28(PIO_4)
I2C_SCL0: J2.10 R11.2 R12.2 R24.2 R25.2 R29.2 R34.2 R61.2 TP9.1(Pin1)
I2C_SCL1: J10.6 R6.2 R7.2 R23.2 R26.2 R30.2 R33.2 R64.2 TP20.1(Pin1)
I2C_SCL_FXAS21000CQ: R25.1 R26.1 U4.11(SCL/SCLK)
I2C_SCL_FXOS8700CQ: R33.1 R34.1 U9.4(SCL/SCLK)
I2C_SCL_MAG3110: R7.1 R12.1 U2.7(SCL)
I2C_SCL_MMA8652FC: R6.1 R11.1 U3.2(SCL)
I2C_SCL_MMA9553_LV: R40.2 U7.3(SCL1) U11.4(SCL0/RGPIO0/SCLK)
I2C_SCL_MMA9553L: R29.1 R30.1 R36.2 U7.6(SCL2)
I2C_SCL_MPL3115A2: R23.1 R24.1 U1.8(SCL)
I2C_SDA0: J2.9 R14.2 R16.2 R19.2 R20.2 R32.2 R39.2 R62.2 TP10.1(Pin1)
I2C_SDA1: J10.5 R10.2 R13.2 R18.2 R21.2 R31.2 R48.2 R63.2 TP19.1(Pin1)
I2C_SDA_FXAS21000CQ: R13.1 R16.1 U4.12(SDA/MOSI)
I2C_SDA_FXOS8700CQ: R39.1 R48.1 U9.6(SDA/MOSI)
I2C_SDA_MAG3110: R18.1 R19.1 U2.6(SDA)
I2C_SDA_MMA8652FC: R20.1 R21.1 U3.10(SDA)
I2C_SDA_MMA9553_LV: R49.2 U7.4(SDA1) U11.6(SDA0/RGPIO1/SDI)
I2C_SDA_MMA9553L: R31.1 R32.1 R37.2 U7.5(SDA2)
I2C_SDA_MPL3115A2: R10.1 R14.1 U1.7(SDA)
I2CSEL_FXAS21000CQ: R4.2 U4.17(I2C/~{SPI})
INT1_ACC: R68.2 U10.11(INT1)
INT1_ACCEL: J4.3 U3.3(INT1)
INT1_COMBO: J3.1 R66.2
INT1_COMBO_R: R66.1 U9.11(INT1)
INT1_GYRO: J6.1 U4.3(INT1)
INT1_PRESSURE: J5.3 U1.6(INT1)
INT1_SPI_ACCEL: J6.3 R68.1
INT2_ACC: R67.2 U10.9(INT2)
INT2_ACCEL: TP33.1(Pin1) U3.5(INT2)
INT2_COMBO: J4.1 R65.2
INT2_COMBO_R: R65.1 U9.9(INT2)
INT2_GYRO: TP32.1(Pin1) U4.2(INT2)
INT2_PRESSURE: TP34.1(Pin1) U1.5(INT2)
INT2_SPI_ACCEL: R67.1 TP31.1(Pin1)
INT_ACCEL: J1.5 J4.2 TP4.1(Pin1)
INT_GYRO: J1.6 J6.2 TP3.1(Pin1)
INT_MAG: J1.3 J3.2 TP6.1(Pin1)
INT_MAG3110: J3.3 U2.9(INT1)
INT_MMA9553L_LV: U11.11(RGPIO5/PDB_A/INT_O) U12.2(A)
INT_PED: J2.1 J5.2 TP17.1(Pin1)
INT_PEDOMETER: J5.1 U12.4(Y)
LSENSE_EMITTER: C39.1 Q2.2(EMITTER) R58.1 R59.1
NC_FRDM_AREF: J2.8
P5-9V_VOUT: J9.8
RGPIO3_MMA9553L: R51.2 U11.8(RGPIO3/SDA1/~{SS})
RST_ACCEL: R46.2 R47.1 U10.16(RST)
RST_BT: C46.1 R2.1 SW5.1(SW1) U5.3(~{RESET})
RST_FXAS21000CQ: R27.2 R28.1 U4.4(~{RST})
RST_FXOS8700CQ: R44.1 R45.1 U9.16(RST)
RST_MMA9553L: R41.2 R42.2 U11.3(~{RESET})
RST_TGTMCU: R2.2 R35.2 R44.2 R46.1 U6.4(OUT)
RST_TGTMCU_B: J9.3 R28.2 R41.1 U6.2(IN)
SA0_FXOS8700CQ: J23.2 R57.2 U9.10(SA1/~{CS})
SA1_FXOS8700CQ: J21.1 R55.2 U9.7(SA0/MISO)
SA_GYRO: J8.2 R5.2 U4.13(SA0/MISO)
SD_CARD_DETECT: J11.G1(SWITCH) TP22.1(Pin1)
SD_CLK: J11.P5(CLK) R9.2
SD_CMD: J11.P3(CMD) R22.2
SD_DAT0: J11.P7(DAT0) R3.2
SD_DAT1: J11.P8(DAT1) TP23.1(Pin1)
SD_DAT2: J11.P1(DAT2) TP24.1(Pin1)
SD_DAT3: J11.P2(CD/DAT3) R1.2 TP21.1(Pin1)
SNS_LIGHT: J10.4 R58.2 TP29.1(Pin1)
SPI_CLK: J2.6 R9.1 TP12.1(Pin1) U10.4(SCL/SCLK)
SPI_MISO: J2.5 R3.1 TP13.1(Pin1) U10.7(SA0/MISO)
SPI_MOSI: J2.4 R22.1 TP14.1(Pin1) U10.6(SDA/MOSI)
SPI_SS_SD: J10.3 R1.1 TP35.1(Pin1)
SPI_SS_SPI_ACCEL: J2.3 TP15.1(Pin1) U10.10(SA1/~{CS})
TP_FRDM_DIG03: J1.4 TP5.1(Pin1)
TP_FRDM_DIG06: J1.7 TP2.1(Pin1)
TP_FRDM_DIG07: J1.8 TP1.1(Pin1)
TP_FRDM_DIG09: J2.2 TP16.1(Pin1)
VREGD_FXAS21000CQ: C8.1 U4.16(VREGD)

Not connected (* = marked no-connect by the designer): J9 1; U2 3(NC)*; U5 2(SBWTCK)* 4(ADC_1)* 5(SPI_MISO)* 6(~{SPI_CS})* 7(SPI_CLK)* 8(SPI_MOSI)* 15(PIO_19)* 16(PIO_20)* 17(PIO_21)* 18(PIO_22)* 19(PIO_14)* 21(ADC_0)* 22(PIO_9)* 24(PIO_5)* 25(PIO_6)* 27(PIO_8)* 29(PIO_7)* 31(NC)* 32(NC)*; U6 1(NC)*; U8 2(NC)* 3(NC)* 6(NC)* 7(NC)*; U9 15(NC)*; U10 8(NC)* 15(NC)*; U11 2(BKGD/MS/RGPIO9)* 7(RGPIO2/SCL1/SDO)* 9(RGPIO4/INT)* 12(RGPIO6/AN0/TPMCH0)* 13(RGPIO7/AN1/TPMCH1)* 15(RGPIO8/PDB_B)*; U12 5(NC)*; U13 2(NC)* 3(NC)* 6(NC)* 7(NC)*; U14 6(~{FAST})*

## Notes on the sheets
sheet 1
- VOLTAGE REGULATION
- IN CIRCUIT
  TEST GND
  PROBING
- Prototyping Area Heading Signals
- Current
  measurement
  header
- Current
  measurement
  header
- SHORTING HEADER
  ON BOTTOM LAYER
- SHORTING HEADER
  ON BOTTOM LAYER
- DEBUG
  GROUND HOOK
- Fixed 1.8V VLDO
  150mV dropout at 300mA
- AUTO-CHARGE
  OPTION
  ALL THE TIME
  USB IS PRESENT
- Li-Ion Battery Charger
- SHORTING HEADER
  ON BOTTOM LAYER
- Tenergy      #033048
  Unionfortune #E603562
  3.7V Li-Ion Polymer
  Rechargeable Battery
- +
  -
- NO SHUNT
- microSD Card Connector, SPI Mode
- Battery Regulation
- Isolation interface
  header
- DEFAULT: 1-X
- ATTENTION!
- PLEASE ENABLE
  PROTECTION DIODE D12
  ON FREEDOM KL25Z BOARD
  REV E OR LATER
  BY OPENING
  J12 SHORTING HEADER
  BEFORE CONNECTING THIS JUMPER
- Fixed 3.3V VLDO
  150mV dropout at 300mA
sheet 2
- Table of Contents
- Revisions & Change Log
- 1
- Title
- Rev
- Description
- Date
- Approved
- 2
- Block Diagram
- X1
- 27909 base Initial Draft
- 03/07/13
- J. SCOTT
- 3
- Sensors
- A
- 27909 Prototype Release
- 03/26/13
- J. SCOTT
- 3
- Power Supply, Battery, uSD
- AX1
- _UD 27982 (BT Version)
         Under Development
- 07/16/13
- J. SCOTT
- AX1
- 27982 (BT Version)
    PPL & A070 RELEASE
- 07/22/13
- J. SCOTT
- AX2
- 27982 (BT Version)
    Block Diagram Update
- 08/07/13
- J. SCOTT
- B
- 27982 (BT Version)
     Release candidate
- 08/23/13
- J. SCOTT
- BX1
- 27982 (UNDER DEVELOPMENT)
     I2C swap fix
- 09/25/13
- J. SCOTT
- C
- 27909 Non BT ver.
   (BOM update per coreid)
   Release to prod.
- 10/02/13
- J. SCOTT
- FRDM-FXS-MULTI
sheet 3
- 1. Unless Otherwise Specified:
- All resistors are in ohms, 5%, 1/8 Watt
- All capacitors are in uF, 20%, 50V
- All voltages are DC
- All polarized capacitors are aluminum electrolytic
- 2. Interrupted lines coded with the same letter or letter
      combinations are electrically connected.
- 3. Device type number is for reference only. The number
      varies with the manufacturer.
- 4. Special signal usage:
- _B Denotes - Active-Low Signal
- <> or [] Denotes - Vectored Signals
- 5. Interpret diagram in accordance with American
  National Standards Institute specifications, current
  revision, with the exception of logic block symbology.
sheet 4
- Fixable
  90° rotation
- BLUETOOTH INTERFACE
- Isolation interface
  header
- FXOS8700CQ COMBO SENSOR
- MAG3110 MAGNETOMETER
- Current
  measurement
  header
- Current
  measurement
  header
- Default: 1-2
- UART RX/TX
  POKA-YOKE:
  Place both
  jumpers flipped
  (opposite) orientation
  and provide same airgap
  between RX to TX jumpers
  terminals in a square fashion.
- CAD NOTE:
- SHORTING HEADER
  ON BOTTOM LAYER
- SHORTING HEADER
  ON BOTTOM LAYER
- SHORTING HEADER
  ON BOTTOM LAYER
- UART RX/TX
  POKA-YOKE
- Default: 1-2
- Default: 1-2
- SHORTING HEADER
  ON BOTTOM LAYER
- SHORTING HEADER
  ON BOTTOM LAYER
- MMA8652FC
  ACCELEROMETER
- Current
  measurement
  header
- SHORTING HEADER
  ON BOTTOM LAYER
- RESET LOGIC INVERTER
- FXAS21000CQ
  GYROSCOPE
- {{OPEN DRAIN INVERTER}}
- INTERRUPT SELECTORS
- SHORTING HEADER
  ON BOTTOM LAYER
- MPL3115A2 PRESSURE SENSOR
- Current measurement
  header
- Current
  measurement
  header
- SHORTING HEADER
  ON BOTTOM LAYER
- SHORTING HEADER
  ON BOTTOM LAYER
- MMA9553L
  PEDOMETER
- {SD_CLK}
- {SD_DAT0}
- {SD_CMD}
- {SD_CD}
- VISIBLE LIGHT SENSOR
- FXLS8471Q SPI
  ACCELEROMETER
- Current
  measurement
  header
- FREEDOM PLATFORM
  COMPATIBLE SHIELDS
- 1.8V - 3.3V
  Level translation
- SHORTING HEADER
  ON BOTTOM LAYER
- 1.8V - 3.3V
  Level translation
